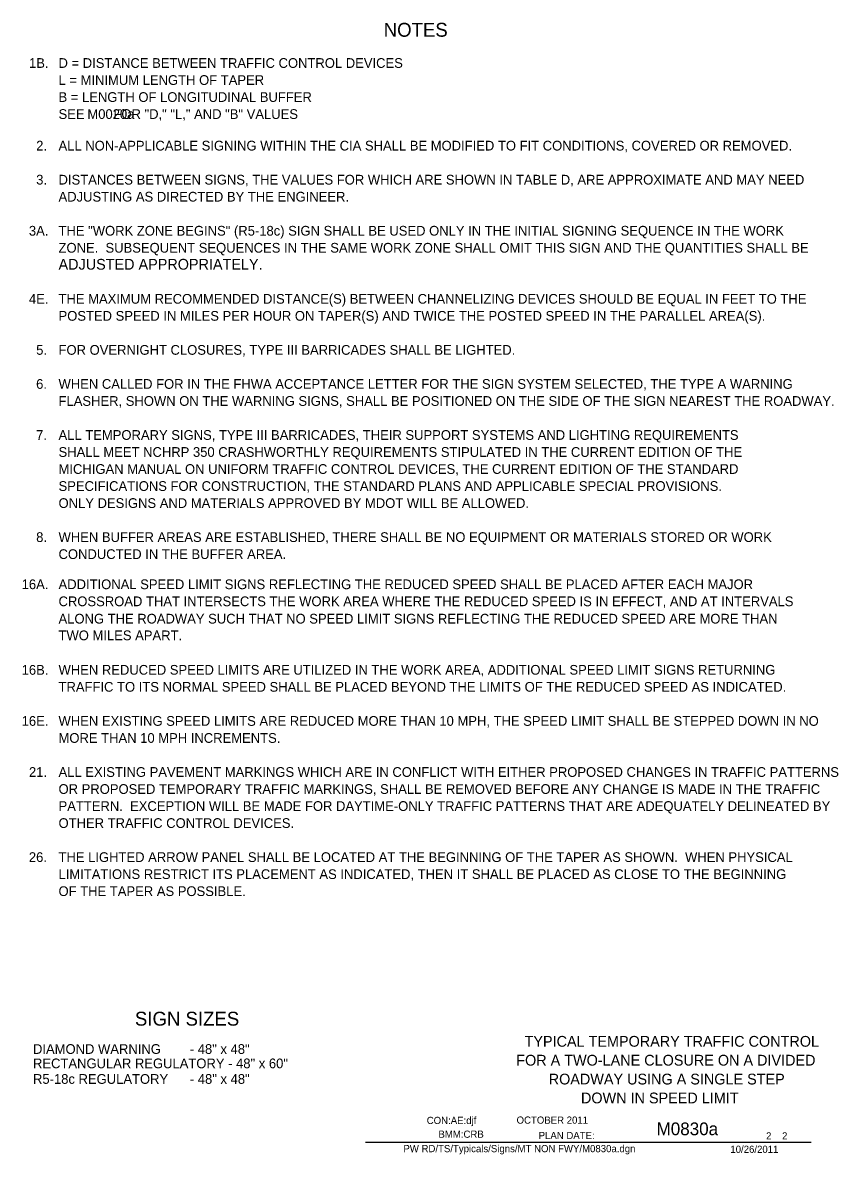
# Model space of a CAD drawing. Extents: x 16727 to 18475, y 5729 to 6909.
# Drawn here: x 17771 to 18475, y 5932 to 6909 of the extents above; entities that cross this region are included whole.
import ezdxf

# ---------------------------------------------------------------- set-up
doc = ezdxf.new("R2010")
doc.units = 0
for name, color, linetype in [('BORDER', 7, 'Continuous'), ('BORDER_SIGNAL_WO', 7, 'Continuous'), ('TYPICAL_TEXT_DIMEN_PR', 7, 'Continuous')]:
    doc.layers.add(name, color=color, linetype=linetype)

msp = doc.modelspace()

# ---------------------------------------------------------------- linework, layer by layer
at = {"layer": 'BORDER'}
msp.add_line((18066.75, 5942.5), (18451.75, 5942.5), dxfattribs=at)

# ---------------------------------------------------------------- texts
for s, height, p in [('TYPICAL TEMPORARY TRAFFIC CONTROL', 9.3, (18204.21, 6024.8)), ('FOR A TWO-LANE CLOSURE ON A DIVIDED', 9.3, (18197.02, 6008.5)), ('ROADWAY USING A SINGLE STEP', 9.3, (18225.04, 5992.2)), ('DOWN IN SPEED LIMIT', 9.3, (18252.92, 5975.9)), ('PLAN DATE:', 6.2, (18216.35, 5945.07)), ('PLAN DATE:', 6.2, (18216.35, 5945.07))]:
    msp.add_text(s, height=height, dxfattribs=at).set_placement(p)
at = {"layer": 'BORDER_SIGNAL_WO'}
for s, height, p in [('CON:AE:djf', 6.2, (18119.69, 5958.06)), ('    OCTOBER 2011    ', 6.2, (18188.08, 5958.34)), ('BMM:CRB   ', 6.2, (18129.81, 5946.17)), ('    M0830a   ', 11, (18301.86, 5948.38)), (' 2    2 ', 6.2, (18410.45, 5944.7)), ('PW RD/TS/Typicals/Signs/MT NON FWY/M0830a.dgn    ', 6.2, (18099.55, 5933.71)), ('10/26/2011    ', 6.2, (18381.93, 5933.13))]:
    msp.add_text(s, height=height, dxfattribs=at).set_placement(p)
at = {"layer": 'TYPICAL_TEXT_DIMEN_PR'}
for s, height, p in [('NOTES', 12, (18082.55, 6897)), ('1B.', 8.4, (17776.19, 6870.11)), ('D = DISTANCE BETWEEN TRAFFIC CONTROL DEVICES', 8.4, (17801.7, 6870.11)), ('L = MINIMUM LENGTH OF TAPER', 8.4, (17801.7, 6855.41)), ('B = LENGTH OF LONGITUDINAL BUFFER', 8.4, (17801.7, 6840.71)), ('SEE        FOR "D," "L," AND "B" VALUES', 8.4, (17801.7, 6826.01)), ('M0020a', 8.4, (17826.62, 6826.01)), ('2.', 8.4, (17782.39, 6798.75)), ('ALL NON-APPLICABLE SIGNING WITHIN THE CIA SHALL BE MODIFIED TO FIT CONDITIONS, COVERED OR REMOVED.', 8.4, (17801.7, 6798.75)), ('3.', 8.4, (17782.39, 6769.35)), ('DISTANCES BETWEEN SIGNS, THE VALUES FOR WHICH ARE SHOWN IN TABLE D, ARE APPROXIMATE AND MAY NEED', 8.4, (17801.7, 6769.35)), ('ADJUSTING AS DIRECTED BY THE ENGINEER.', 8.4, (17801.7, 6754.65)), ('THE "WORK ZONE BEGINS" (R5-18c) SIGN SHALL BE USED ONLY IN THE INITIAL SIGNING SEQUENCE IN THE WORK', 8.4, (17801.7, 6725.25)), ('3A.', 8.4, (17776.09, 6725.25)), ('ZONE.  SUBSEQUENT SEQUENCES IN THE SAME WORK ZONE SHALL OMIT THIS SIGN AND THE QUANTITIES SHALL BE', 8.4, (17801.7, 6710.55)), ('ADJUSTED APPROPRIATELY.', 9.3, (17801.7, 6695.85)), ('THE MAXIMUM RECOMMENDED DISTANCE(S) BETWEEN CHANNELIZING DEVICES SHOULD BE EQUAL IN FEET TO THE', 8.4, (17801.7, 6666.45)), ('4E.', 8.4, (17776.13, 6666.45)), ('POSTED SPEED IN MILES PER HOUR ON TAPER(S) AND TWICE THE POSTED SPEED IN THE PARALLEL AREA(S).', 8.4, (17801.7, 6651.75)), ('5.', 8.4, (17782.39, 6622.35)), ('FOR OVERNIGHT CLOSURES, TYPE III BARRICADES SHALL BE LIGHTED.', 8.4, (17801.7, 6622.35)), ('6.', 8.4, (17782.34, 6592.95)), ('WHEN CALLED FOR IN THE FHWA ACCEPTANCE LETTER FOR THE SIGN SYSTEM SELECTED, THE TYPE A WARNING ', 8.4, (17801.7, 6592.95)), ('FLASHER, SHOWN ON THE WARNING SIGNS, SHALL BE POSITIONED ON THE SIDE OF THE SIGN NEAREST THE ROADWAY.', 8.4, (17801.7, 6578.25)), ('7.', 8.4, (17782.34, 6548.86)), ('ALL TEMPORARY SIGNS, TYPE III BARRICADES, THEIR SUPPORT SYSTEMS AND LIGHTING REQUIREMENTS', 8.4, (17801.7, 6548.88)), ('SHALL MEET NCHRP 350 CRASHWORTHLY REQUIREMENTS STIPULATED IN THE CURRENT EDITION OF THE', 8.4, (17801.7, 6534.18)), ('MICHIGAN MANUAL ON UNIFORM TRAFFIC CONTROL DEVICES, THE CURRENT EDITION OF THE STANDARD', 8.4, (17801.7, 6519.48)), ('SPECIFICATIONS FOR CONSTRUCTION, THE STANDARD PLANS AND APPLICABLE SPECIAL PROVISIONS.', 8.4, (17801.7, 6504.78)), ('ONLY DESIGNS AND MATERIALS APPROVED BY MDOT WILL BE ALLOWED.', 8.4, (17801.7, 6490.07)), ('8.', 8.4, (17782.39, 6460.68)), ('WHEN BUFFER AREAS ARE ESTABLISHED, THERE SHALL BE NO EQUIPMENT OR MATERIALS STORED OR WORK     ', 8.4, (17801.7, 6460.68)), ('CONDUCTED IN THE BUFFER AREA.', 8.4, (17801.7, 6445.98)), ('16A.', 8.4, (17769.83, 6419.94)), ('ADDITIONAL SPEED LIMIT SIGNS REFLECTING THE REDUCED SPEED SHALL BE PLACED AFTER EACH MAJOR', 8.4, (17801.7, 6419.94)), ('CROSSROAD THAT INTERSECTS THE WORK AREA WHERE THE REDUCED SPEED IS IN EFFECT, AND AT INTERVALS', 8.4, (17801.7, 6405.24)), ('ALONG THE ROADWAY SUCH THAT NO SPEED LIMIT SIGNS REFLECTING THE REDUCED SPEED ARE MORE THAN', 8.4, (17801.7, 6390.24)), ('TWO MILES APART.', 8.4, (17801.7, 6375.84)), ('16B.', 8.4, (17769.84, 6346.03)), ('WHEN REDUCED SPEED LIMITS ARE UTILIZED IN THE WORK AREA, ADDITIONAL SPEED LIMIT SIGNS RETURNING', 8.4, (17801.7, 6346.08)), ('TRAFFIC TO ITS NORMAL SPEED SHALL BE PLACED BEYOND THE LIMITS OF THE REDUCED SPEED AS INDICATED.', 8.4, (17801.7, 6331.38)), ('16E.', 8.4, (17769.84, 6301.93)), ('WHEN EXISTING SPEED LIMITS ARE REDUCED MORE THAN 10 MPH, THE SPEED LIMIT SHALL BE STEPPED DOWN IN NO', 8.4, (17801.7, 6301.93)), ('MORE THAN 10 MPH INCREMENTS.', 8.4, (17801.7, 6287.23)), ('21.', 8.4, (17776.14, 6257.83)), ('ALL EXISTING PAVEMENT MARKINGS WHICH ARE IN CONFLICT WITH EITHER PROPOSED CHANGES IN TRAFFIC PATTERNS', 8.4, (17801.7, 6257.83)), ('OR PROPOSED TEMPORARY TRAFFIC MARKINGS, SHALL BE REMOVED BEFORE ANY CHANGE IS MADE IN THE TRAFFIC', 8.4, (17801.7, 6243.13)), ('PATTERN.  EXCEPTION WILL BE MADE FOR DAYTIME-ONLY TRAFFIC PATTERNS THAT ARE ADEQUATELY DELINEATED BY', 8.4, (17801.7, 6228.43)), ('OTHER TRAFFIC CONTROL DEVICES.', 8.4, (17801.7, 6213.73)), ('26.', 8.4, (17776.09, 6184.33)), ('THE LIGHTED ARROW PANEL SHALL BE LOCATED AT THE BEGINNING OF THE TAPER AS SHOWN.  WHEN PHYSICAL', 8.4, (17801.7, 6184.33)), ('LIMITATIONS RESTRICT ITS PLACEMENT AS INDICATED, THEN IT SHALL BE PLACED AS CLOSE TO THE BEGINNING', 8.4, (17801.7, 6169.63)), ('OF THE TAPER AS POSSIBLE.', 8.4, (17801.7, 6154.93)), ('SIGN SIZES', 12, (17867.69, 6043)), ('DIAMOND WARNING        - 48" x 48"', 8.4, (17779.65, 6018.6)), ('RECTANGULAR REGULATORY - 48" x 60"', 8.4, (17779.65, 6006.2)), ('R5-18c REGULATORY      - 48" x 48"', 8.4, (17779.65, 5992.75))]:
    msp.add_text(s, height=height, dxfattribs=at).set_placement(p)

doc.saveas('drawing.dxf')
